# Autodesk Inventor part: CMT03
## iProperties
Created: 2006-10
Part Number: CMT03
Document SubType Name: Modeling
Designer: Lab User
Author: Lab User
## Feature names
1. Extrusion1
2. Hole1
3. Extrusion2
